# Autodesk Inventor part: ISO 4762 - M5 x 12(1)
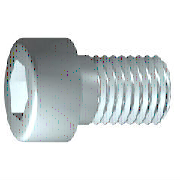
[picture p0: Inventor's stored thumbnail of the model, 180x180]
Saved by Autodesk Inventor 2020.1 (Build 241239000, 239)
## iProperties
Created: 2019-01
Part Number: ISO 4762 - M5 x 12(1)
Material: Edelstahl, 440C
Description: Innensechskantschraube
Document SubType Name: Modeling
Standard: ISO 4762
Designer: lutzd
Standard Revision: Fourth edition 2004-03-01
Standards Organization: ISO
Language: de-DE
Size Designation: M5 x 12
Categories: <MemberInstance><Categories><Category DisplayName="Verbindungselemente" InternalName="e4da775c-781d-43d5-af7c-5136215cf5a6" Mnemonic="FSTN"><Category DisplayNam
Mass: 3.67607 g
Surface Area: 4.62573 cm^2
Volume: 0.474332 cm^3
Density: 7.75 g/cm^3
Appearance: Halbpoliert
IsCustomPart: 0
Author: lutzd
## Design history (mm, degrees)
body "Solid1"
sketch "Skizze1"
  geometry: L1 (-1.167, 0)-(12, 0); L2 (12, 0)-(12, 2.5); L3 (12, 2.5)-(2, 2.5); L4 (2, 2.5)-(1.509, 2.5); L5 (1.509, 2.5)-(0, 2.5); L6 (0, 2.5)-(0, 4.25); L7 (0, 4.25)-(-5, 4.25); L8 (-5, 4.25)-(-5, 2.309); L9 (-5, 2.309)-(-2.5, 2.309); L10 (-2.5, 2.309)-(-1.167, 0); L11 (-8.4, 0)-(15.4, 0) reference; L12 (0, -0.85)-(0, 5.1) reference; L13 (2, 2.5)-(0, 2.5)
  constraints: 22 end point, 6 parallel, 2 collinear, 2 perpendicular, 1 horizontal, 1 point on line
  dimensions: "d1" = 10 distance from line of L3.end L2 (= GEL); "d2" = 0.49086 distance of L4.end L3.end (computed from GAL); "d3" = 5 distance between parallel lines of L8 L6 (= KOH); "d4" = 2.5 distance of L8.end L9.end (= INTI); "d5" = 60 deg angle of L10 L1; "d6" = 5 diameter of L3 L1 (= GD); "d7" = 5 diameter of L5 L1 (= BDM); "d8" = 4.6188 diameter of L9 L1 (= 1.1547 x SW); "d9" = 8.5 diameter of L7 L1 (= KOD); "d26" = 12 distance between parallel lines of L12 L2 (= NLG)
workplane "Work Plane1"
fillet "Fillet2" dims "d30" = 0.1 (= R)
revolve "Körper" stored, may be unused: angle "d10" = 90 deg
sketch "Skizze2"
  geometry: L1 (0, -5.95)-(0, 5.95) reference; L2 (-5.95, 0)-(5.95, 0) reference; L3 (2.309, 0)-(1.155, -2); L4 (1.155, -2)-(-1.155, -2); L5 (-1.155, -2)-(-2.309, 0); L6 (-2.309, 0)-(-1.155, 2); L7 (-1.155, 2)-(1.155, 2); L8 (1.155, 2)-(2.309, 0); 2 further points
  constraints: 12 end point, 1 coincident, 1 horizontal alignment, 1 point on line, 12 other
extrude "Loch" join sketch "Skizze2" stored distance "d11" = 10; taper "d12" = 0 deg
fillet "Rundung1" dims "d17" = 0.5 (= RR)
feature "Gewinde" dims "d13" = 10 (= GEL), "d14" = 0
chamfer "Fase1" distance "d15" = 0.49076 (= -0.5 x SPD + 0.5 x GD); stored, may be unused: second distance "d16" = 0.49076 (= GUL), angle "d27" = 45 deg
other parameters: "GD" = 5 [user parameter; used in 2 equation terms], "NLG" = 12 [user parameter; used in 1 equation term], "GEL" = 10 [user parameter; used in 2 equation terms], "KOD" = 8.5 [user parameter; used in 1 equation term], "KOH" = 5 [user parameter; used in 1 equation term], "INTI" = 2.5 [user parameter; used in 1 equation term], "GAL" = 0.49076 (= 0.61345 x PTC) [user parameter; used in 1 equation term], "GUL" = 0.49076 (= 0.61345 x PTC) [user parameter; used in 1 equation term], "BDM" = 5 (= NND) [user parameter; used in 1 equation term], "SW" = 4 [user parameter; used in 2 equation terms], "RR" = 0.5 [user parameter; used in 1 equation term], "SPD" = 4.01848 (= NND - 1.2269 x PTC) [user parameter; used in 1 equation term], "d19" = 0, "d28" = 0, "d29" = 0, "R" = 0.1 [user parameter; used in 1 equation term], "TOA" = 30 deg [user parameter], "GD1" = 4.01848 (= THREADDIA - 1.2269 x PTC) [user parameter], "THREADDIA" = 5 [user parameter; used in 1 equation term], "FAWI" = 45 deg [user parameter], "TPU" = 12.5 (computed from PTC) [user parameter], "PTC" = 0.8 [user parameter; used in 5 equation terms], "NND" = 5 [user parameter; used in 2 equation terms], "E0" = 4.62 (= 1.155 x SW) [user parameter]
